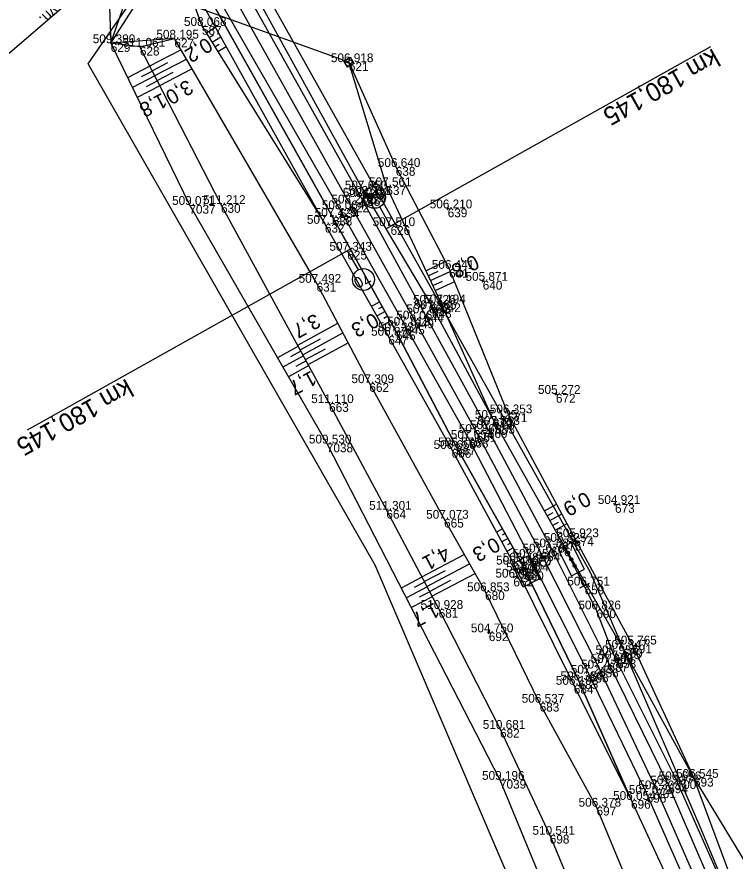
# Model space of a CAD drawing. Extents: x -1234191 to 23050, y -1290331 to -741191.
# Drawn here: x -865261.3 to -865163.3, y -1106049.8 to -1105934.7 of the extents above; entities that cross this region are included whole.
import ezdxf

# ---------------------------------------------------------------- set-up
doc = ezdxf.new("R2010")
doc.units = 0
for name, color, linetype in [('Vrstva 1', 7, 'Continuous'), ('Vrstva 25', 7, 'Continuous'), ('Vrstva 36', 7, 'Continuous'), ('Vrstva 4', 7, 'Continuous'), ('Vrstva 48', 7, 'Continuous'), ('Vrstva 49', 7, 'Continuous'), ('Vrstva 5', 7, 'Continuous'), ('Vrstva 51', 7, 'Continuous'), ('Vrstva 53', 7, 'Continuous'), ('Vrstva 55', 7, 'Continuous'), ('Vrstva 60', 7, 'Continuous'), ('Vrstva 61', 7, 'Continuous'), ('Vrstva 7', 7, 'Continuous')]:
    doc.layers.add(name, color=color, linetype=linetype)

msp = doc.modelspace()

# ---------------------------------------------------------------- linework, layer by layer
at = {"layer": 'Vrstva 1'}
msp.add_lwpolyline([(-865311.67, -1105789.32), (-865293.8, -1105821.19), (-865269.3, -1105864.9), (-865244.89, -1105908.45), (-865242.92, -1105911.97), (-865241.31, -1105914.84), (-865239.97, -1105917.2), (-865237.77, -1105921.12), (-865236.43, -1105923.5), (-865235.71, -1105924.79), (-865215.93, -1105960.12), (-865207.08, -1105975.94), (-865198.56, -1105991.42), (-865189.87, -1106007.72), (-865181.88, -1106023.53), (-865174.08, -1106040), (-865166.92, -1106056.41)], dxfattribs=at)
at = {"layer": 'Vrstva 25'}
msp.add_line((-865216, -1105940.86), (-865305.81, -1105908.49), dxfattribs=at)
at = {"layer": 'Vrstva 36'}
for p, q in [((-865216.62, -1105940.77), (-865215.42, -1105941.11)), ((-865216.28, -1105940.45), (-865215.54, -1105940.66)), ((-865216.35, -1105941.26), (-865215.91, -1105941.39))]:
    msp.add_line(p, q, dxfattribs=at)
msp.add_lwpolyline([(-865215.81, -1105940.18), (-865215.32, -1105941.05), (-865216.19, -1105941.54), (-865216.68, -1105940.67), (-865215.81, -1105940.18)], dxfattribs=at)
at = {"layer": 'Vrstva 4'}
for points in [[(-865236.51, -1105919.7), (-865214.37, -1105959.25), (-865205.71, -1105975.1), (-865197.04, -1105990.91), (-865188.45, -1106007.02), (-865180.58, -1106022.78), (-865172.44, -1106039.34), (-865165.47, -1106055.61), (-865156.6, -1106078.95), (-865148.77, -1106102.82), (-865142.37, -1106126.99), (-865137.15, -1106151.58), (-865133.37, -1106176.49), (-865130.91, -1106201.27), (-865129.85, -1106218.85), (-865129.68, -1106236.02), (-865129.85, -1106253.8), (-865130.86, -1106271.38), (-865132.17, -1106288.96), (-865133.64, -1106306.37), (-865136.71, -1106335.02), (-865140.22, -1106364.77), (-865141.26, -1106380.09)], [(-865164.28, -1106054.67), (-865171.3, -1106038.77), (-865179.91, -1106021.58), (-865182.25, -1106015.47), (-865186.96, -1106006.27), (-865196.36, -1105989.49), (-865204.8, -1105973.8), (-865214.1, -1105958.2), (-865230.93, -1105927.64), (-865233.02, -1105923.82), (-865233.43, -1105924.05), (-865235.15, -1105921.01), (-865234.74, -1105920.78), (-865236.51, -1105919.7)], [(-865168.18, -1106056.94), (-865175.38, -1106040.63), (-865183.27, -1106024.24), (-865191.23, -1106008.42), (-865199.64, -1105992.22), (-865208.33, -1105976.78), (-865217.24, -1105960.91), (-865239.73, -1105921.76), (-865239.36, -1105923.22), (-865237.67, -1105926.18), (-865238.09, -1105926.42), (-865236.15, -1105929.98), (-865218.21, -1105961.95), (-865209.58, -1105977.54), (-865201.36, -1105993.24), (-865192.55, -1106008.96), (-865184.68, -1106025.13), (-865177.51, -1106041.45), (-865169.99, -1106057.67)]]:
    msp.add_lwpolyline(points, dxfattribs=at)
at = {"layer": 'Vrstva 48'}
for p, q in [((-865235.44, -1105936.86), (-865234.19, -1105936.08)), ((-865235.05, -1105937.5), (-865234.44, -1105937.12)), ((-865234.65, -1105938.14), (-865233.46, -1105937.4)), ((-865234.26, -1105938.77), (-865233.68, -1105938.41)), ((-865243.16, -1105941.35), (-865238.91, -1105939.16)), ((-865233.86, -1105939.41), (-865232.73, -1105938.71)), ((-865242.47, -1105942.68), (-865238.16, -1105940.46)), ((-865243.13, -1105941.4), (-865246.19, -1105942.98)), ((-865242.82, -1105942.02), (-865240.68, -1105940.91)), ((-865241.79, -1105944.02), (-865237.4, -1105941.75)), ((-865242.45, -1105942.74), (-865245.53, -1105944.33)), ((-865242.79, -1105942.07), (-865244.32, -1105942.86)), ((-865242.13, -1105943.35), (-865239.96, -1105942.23)), ((-865241.76, -1105944.07), (-865244.87, -1105945.68)), ((-865242.1, -1105943.4), (-865243.65, -1105944.2)), ((-865205.5, -1105969.29), (-865202.85, -1105968.05)), ((-865205.18, -1105969.97), (-865203.84, -1105969.34)), ((-865204.86, -1105970.65), (-865202.19, -1105969.4)), ((-865204.54, -1105971.33), (-865203.22, -1105970.71)), ((-865204.22, -1105972.01), (-865201.62, -1105970.79)), ((-865211.79, -1105973.54), (-865212.89, -1105974.15)), ((-865211.07, -1105974.86), (-865212.15, -1105975.46)), ((-865211.43, -1105974.2), (-865211.97, -1105974.5)), ((-865222.98, -1105979.44), (-865217.5, -1105976.45)), ((-865210.34, -1105976.17), (-865211.41, -1105976.76)), ((-865210.7, -1105975.51), (-865211.24, -1105975.81)), ((-865222.63, -1105980.09), (-865219.89, -1105978.6)), ((-865222.27, -1105980.75), (-865216.8, -1105977.78)), ((-865222.89, -1105979.6), (-865225.74, -1105981.15)), ((-865221.91, -1105981.41), (-865219.18, -1105979.93)), ((-865221.55, -1105982.07), (-865216.1, -1105979.11)), ((-865222.18, -1105980.92), (-865224.99, -1105982.45)), ((-865222.54, -1105980.26), (-865223.95, -1105981.03)), ((-865221.82, -1105981.58), (-865223.22, -1105982.34)), ((-865221.46, -1105982.24), (-865224.24, -1105983.75)), ((-865189.32, -1106002.05), (-865187.67, -1106001.13)), ((-865188.95, -1106002.71), (-865188.14, -1106002.25)), ((-865188.59, -1106003.36), (-865186.96, -1106002.45)), ((-865188.22, -1106004.02), (-865187.41, -1106003.57)), ((-865187.85, -1106004.67), (-865186.25, -1106003.78)), ((-865195.06, -1106004.49), (-865195.86, -1106004.94)), ((-865194.69, -1106005.14), (-865195.09, -1106005.37)), ((-865194.32, -1106005.79), (-865195.14, -1106006.26)), ((-865193.59, -1106007.1), (-865194.43, -1106007.57)), ((-865193.96, -1106006.45), (-865194.37, -1106006.68)), ((-865206.06, -1106011.02), (-865200.27, -1106007.97)), ((-865205.36, -1106012.35), (-865199.53, -1106009.28)), ((-865205.71, -1106011.69), (-865202.81, -1106010.16)), ((-865204.67, -1106013.68), (-865198.79, -1106010.58)), ((-865206.03, -1106011.08), (-865208.85, -1106012.57)), ((-865205.68, -1106011.75), (-865207.09, -1106012.49)), ((-865205.02, -1106013.02), (-865202.09, -1106011.47)), ((-865205.33, -1106012.41), (-865208.16, -1106013.9)), ((-865204.98, -1106013.07), (-865206.4, -1106013.82)), ((-865204.64, -1106013.74), (-865207.47, -1106015.23))]:
    msp.add_line(p, q, dxfattribs=at)
at = {"layer": 'Vrstva 49'}
for p, q in [((-865239.79, -1105937.65), (-865248.48, -1105938.27)), ((-865244.5, -1105938.75), (-865248.48, -1105938.27)), ((-865244.5, -1105938.75), (-865239.79, -1105937.65)), ((-865202.76, -1105960.73), (-865202.27, -1105960.86)), ((-865202.45, -1105960.55), (-865202.58, -1105961.04)), ((-865197.98, -1105970.6), (-865197.5, -1105970.74)), ((-865197.67, -1105970.43), (-865197.8, -1105970.91)), ((-865188, -1105986.02), (-865187.52, -1105986.16)), ((-865187.69, -1105985.85), (-865187.83, -1105986.33)), ((-865179.94, -1106001.03), (-865179.46, -1106001.17)), ((-865179.62, -1106000.86), (-865179.77, -1106001.34)), ((-865197.15, -1106018.52), (-865196.67, -1106018.68)), ((-865196.83, -1106018.36), (-865196.99, -1106018.84))]:
    msp.add_line(p, q, dxfattribs=at)
for points in [[(-865239.87, -1105923.51), (-865244.4, -1105924.73), (-865248.77, -1105929.71), (-865248.48, -1105938.27)], [(-865248.48, -1105938.27), (-865245.36, -1105929.31), (-865242.58, -1105925.9), (-865239.87, -1105923.51)], [(-865248.48, -1105938.27), (-865244.7, -1105932.37), (-865240.18, -1105924.98)], [(-865177.51, -1106041.45), (-865185.32, -1106025.75), (-865193.46, -1106009.36), (-865201.99, -1105993.6), (-865210.62, -1105978.16), (-865219.27, -1105962.9), (-865235.91, -1105933), (-865239.58, -1105926.15)], [(-865239.58, -1105926.15), (-865236.03, -1105935.92), (-865219.27, -1105962.9)], [(-865177.51, -1106041.45), (-865184.68, -1106025.13), (-865192.55, -1106008.96), (-865201.36, -1105993.24), (-865209.58, -1105977.54), (-865218.21, -1105961.95), (-865236.15, -1105929.98), (-865238.09, -1105926.42)], [(-865248.48, -1105938.27), (-865237.75, -1105960.32), (-865219, -1105992.85), (-865195.39, -1106038.71), (-865183.02, -1106068.8), (-865169.19, -1106106.68), (-865159.48, -1106146.73), (-865152.52, -1106195.61), (-865150.4, -1106228.21), (-865150, -1106273.86), (-865151.77, -1106298.15), (-865154.53, -1106323.47), (-865155.1, -1106347.33), (-865155.48, -1106356.04)], [(-865145.94, -1106363.57), (-865142.64, -1106334.62), (-865139.29, -1106305.46), (-865137.62, -1106288.58), (-865139.33, -1106271.91), (-865139.98, -1106253.67), (-865139.71, -1106236.34), (-865140.16, -1106218.63), (-865140.5, -1106202.16), (-865143.15, -1106177.89), (-865147.63, -1106152.54), (-865151.89, -1106128.68), (-865158.01, -1106106.65), (-865166.09, -1106083.22), (-865174.81, -1106060.27), (-865182.22, -1106042.37), (-865189.98, -1106028.2), (-865197.42, -1106013), (-865203.01, -1106003.11), (-865213.2, -1105984.62), (-865220.4, -1105970.94), (-865239.79, -1105937.65)], [(-865155.48, -1106356.04), (-865151.68, -1106354.48), (-865149.3, -1106324.02), (-865147.43, -1106302.26), (-865147.23, -1106283.88), (-865146.7, -1106266.35), (-865146.43, -1106254.76), (-865146.52, -1106236.51), (-865147.19, -1106221.06), (-865147.91, -1106203.33), (-865150.13, -1106177.77), (-865154.11, -1106153.82), (-865158.52, -1106132.86), (-865164.63, -1106109.25), (-865174.13, -1106081.15), (-865182.3, -1106061.24), (-865188.6, -1106046.2), (-865195.38, -1106031.76), (-865203.75, -1106015.41), (-865210.88, -1106001.89), (-865218.69, -1105987.34), (-865233.44, -1105960.2), (-865244.5, -1105938.75)], [(-865127.37, -1106218.56), (-865127, -1106201.04), (-865129.61, -1106175.31), (-865133.23, -1106150.78), (-865138.55, -1106126.31), (-865140.86, -1106117.48), (-865147.92, -1106094.71), (-865153.79, -1106077.74), (-865163.01, -1106054.44), (-865168.93, -1106038.44), (-865178.61, -1106020.85), (-865186.96, -1106006.27), (-865196.36, -1105989.49), (-865203.41, -1105973.74), (-865210.89, -1105957.77), (-865216, -1105940.86)], [(-865216, -1105940.86), (-865209.6, -1105955.15), (-865202.33, -1105969.04), (-865194.33, -1105988.74), (-865185.26, -1106005.63), (-865177.36, -1106020.26), (-865168.93, -1106038.44), (-865158.94, -1106054.9), (-865150.77, -1106078.05), (-865143.25, -1106101.54), (-865134.36, -1106126.45), (-865131.26, -1106149.56), (-865127.17, -1106172.7), (-865123.9, -1106198.3), (-865127.37, -1106218.56)]]:
    msp.add_lwpolyline(points, dxfattribs=at)
at = {"layer": 'Vrstva 5'}
for p, q in [((-865166.69, -1105938.77), (-865210.31, -1105963.21)), ((-865210.31, -1105963.21), (-865211.77, -1105960.59)), ((-865210.96, -1105963.58), (-865209.65, -1105962.84)), ((-865259.83, -1105991.01), (-865216.21, -1105966.57)), ((-865215.56, -1105966.2), (-865216.86, -1105966.93)), ((-865216.21, -1105966.57), (-865214.74, -1105969.18))]:
    msp.add_line(p, q, dxfattribs=at)
for centre in [(-865212.51, -1105959.28), (-865214.01, -1105970.49)]:
    msp.add_circle(centre, 1.5, dxfattribs=at)
at = {"layer": 'Vrstva 53'}
for points in [[(-865227.66, -1105917.88), (-865232.36, -1105922.35), (-865183.09, -1106010.41), (-865167.99, -1106045.38), (-865144.78, -1106101.17), (-865131.99, -1106166.39), (-865125.85, -1106219.01), (-865125.39, -1106238.65), (-865125.96, -1106278.9), (-865132.87, -1106334.65), (-865136.85, -1106381.38), (-865151.63, -1106445.1), (-865163.44, -1106490.83), (-865178.82, -1106535.04), (-865200.93, -1106584.09), (-865238.82, -1106657.44), (-865256.95, -1106698.52)], [(-865292.28, -1106759.44), (-865281, -1106690.92), (-865292.09, -1106688.29), (-865256.12, -1106617.24), (-865192.39, -1106497.22), (-865182.07, -1106466.18), (-865172.59, -1106441.08), (-865160.97, -1106443.62), (-865159.33, -1106435.02), (-865146.44, -1106359.55), (-865157.51, -1106356.95), (-865157, -1106331.91), (-865151.9, -1106265.92), (-865152.14, -1106213.17), (-865160.59, -1106155.82), (-865173.12, -1106100.65), (-865192.84, -1106055.27), (-865212.4, -1106009.43), (-865251.57, -1105941.08), (-865241.97, -1105927.13)]]:
    msp.add_lwpolyline(points, dxfattribs=at)
at = {"layer": 'Vrstva 55'}
msp.add_lwpolyline([(-865243.93, -1105923.83), (-865276.72, -1105952), (-865303.41, -1105968.16)], dxfattribs=at)
at = {"layer": 'Vrstva 60'}
for p, q in [((-865236.03, -1105935.92), (-865236.03, -1105935.92)), ((-865248.48, -1105938.27), (-865248.48, -1105938.27)), ((-865239.79, -1105937.65), (-865239.79, -1105937.65)), ((-865244.5, -1105938.75), (-865244.5, -1105938.75)), ((-865216, -1105940.86), (-865216, -1105940.86)), ((-865209.6, -1105955.15), (-865209.6, -1105955.15)), ((-865210.89, -1105957.77), (-865210.89, -1105957.77)), ((-865214.1, -1105958.2), (-865214.1, -1105958.2)), ((-865213.6, -1105958.96), (-865213.6, -1105958.96)), ((-865237.75, -1105960.32), (-865237.75, -1105960.32)), ((-865233.44, -1105960.2), (-865233.44, -1105960.2)), ((-865215.93, -1105960.12), (-865215.93, -1105960.12)), ((-865214.37, -1105959.25), (-865214.37, -1105959.25)), ((-865217.24, -1105960.91), (-865217.24, -1105960.91)), ((-865202.52, -1105960.79), (-865202.52, -1105960.79)), ((-865218.21, -1105961.95), (-865218.21, -1105961.95)), ((-865219.27, -1105962.9), (-865219.27, -1105962.9)), ((-865210.31, -1105963.21), (-865210.31, -1105963.21)), ((-865216.21, -1105966.57), (-865216.21, -1105966.57)), ((-865202.33, -1105969.04), (-865202.33, -1105969.04)), ((-865197.74, -1105970.67), (-865197.74, -1105970.67)), ((-865220.4, -1105970.94), (-865220.4, -1105970.94)), ((-865204.8, -1105973.8), (-865204.8, -1105973.8)), ((-865203.41, -1105973.74), (-865203.41, -1105973.74)), ((-865205.71, -1105975.1), (-865205.71, -1105975.1)), ((-865204.67, -1105974.52), (-865204.67, -1105974.52)), ((-865207.08, -1105975.94), (-865207.08, -1105975.94)), ((-865209.58, -1105977.54), (-865209.58, -1105977.54)), ((-865208.33, -1105976.78), (-865208.33, -1105976.78)), ((-865210.62, -1105978.16), (-865210.62, -1105978.16)), ((-865213.2, -1105984.62), (-865213.2, -1105984.62)), ((-865187.76, -1105986.09), (-865187.76, -1105986.09)), ((-865218.69, -1105987.34), (-865218.69, -1105987.34)), ((-865194.33, -1105988.74), (-865194.33, -1105988.74)), ((-865196.36, -1105989.49), (-865196.36, -1105989.49)), ((-865198.56, -1105991.42), (-865198.56, -1105991.42)), ((-865197.04, -1105990.91), (-865197.04, -1105990.91)), ((-865196.03, -1105990.31), (-865196.03, -1105990.31)), ((-865199.64, -1105992.22), (-865199.64, -1105992.22)), ((-865219, -1105992.85), (-865219, -1105992.85)), ((-865201.99, -1105993.6), (-865201.99, -1105993.6)), ((-865201.36, -1105993.24), (-865201.36, -1105993.24)), ((-865179.7, -1106001.1), (-865179.7, -1106001.1)), ((-865210.88, -1106001.89), (-865210.88, -1106001.89)), ((-865203.01, -1106003.11), (-865203.01, -1106003.11)), ((-865186.96, -1106006.27), (-865186.96, -1106006.27)), ((-865185.26, -1106005.63), (-865185.26, -1106005.63)), ((-865188.45, -1106007.02), (-865188.45, -1106007.02)), ((-865191.23, -1106008.42), (-865191.23, -1106008.42)), ((-865189.87, -1106007.72), (-865189.87, -1106007.72)), ((-865193.46, -1106009.36), (-865193.46, -1106009.36)), ((-865192.55, -1106008.96), (-865192.55, -1106008.96)), ((-865192.1, -1106010.3), (-865192.1, -1106010.3)), ((-865193.56, -1106011.14), (-865193.56, -1106011.14)), ((-865197.42, -1106013), (-865197.42, -1106013)), ((-865183.85, -1106012.22), (-865183.85, -1106012.22)), ((-865203.75, -1106015.41), (-865203.75, -1106015.41)), ((-865182.25, -1106015.47), (-865182.25, -1106015.47)), ((-865196.91, -1106018.6), (-865196.91, -1106018.6)), ((-865178.61, -1106020.85), (-865178.61, -1106020.85)), ((-865177.36, -1106020.26), (-865177.36, -1106020.26)), ((-865179.91, -1106021.58), (-865179.91, -1106021.58)), ((-865179.5, -1106022.28), (-865179.5, -1106022.28)), ((-865181.88, -1106023.53), (-865181.88, -1106023.53)), ((-865180.58, -1106022.78), (-865180.58, -1106022.78)), ((-865183.27, -1106024.24), (-865183.27, -1106024.24)), ((-865185.32, -1106025.75), (-865185.32, -1106025.75)), ((-865184.68, -1106025.13), (-865184.68, -1106025.13)), ((-865189.98, -1106028.2), (-865189.98, -1106028.2)), ((-865195.38, -1106031.76), (-865195.38, -1106031.76)), ((-865168.93, -1106038.44), (-865168.93, -1106038.44)), ((-865195.39, -1106038.71), (-865195.39, -1106038.71)), ((-865172.44, -1106039.34), (-865172.44, -1106039.34)), ((-865171.3, -1106038.77), (-865171.3, -1106038.77)), ((-865175.38, -1106040.63), (-865175.38, -1106040.63)), ((-865174.08, -1106040), (-865174.08, -1106040)), ((-865177.51, -1106041.45), (-865177.51, -1106041.45)), ((-865182.22, -1106042.37), (-865182.22, -1106042.37)), ((-865188.6, -1106046.2), (-865188.6, -1106046.2))]:
    msp.add_line(p, q, dxfattribs=at)
at = {"layer": 'Vrstva 7'}
for p, q in [((-865213.16, -1105958.72), (-865214.03, -1105959.21)), ((-865213.84, -1105958.53), (-865213.35, -1105959.4)), ((-865204.91, -1105974.08), (-865204.42, -1105974.96)), ((-865204.23, -1105974.27), (-865205.1, -1105974.76)), ((-865195.59, -1105990.07), (-865196.47, -1105990.55)), ((-865196.26, -1105989.87), (-865195.79, -1105990.75)), ((-865186.06, -1106007.56), (-865186.18, -1106007.94)), ((-865185.6, -1106008.46), (-865185.72, -1106008.83)), ((-865185.15, -1106009.35), (-865185.27, -1106009.73)), ((-865193.56, -1106011.14), (-865193, -1106010.86)), ((-865192.12, -1106010.25), (-865192.08, -1106010.34)), ((-865184.52, -1106012.55), (-865183.19, -1106011.88)), ((-865179.05, -1106022.06), (-865179.95, -1106022.51)), ((-865179.73, -1106021.84), (-865179.28, -1106022.73))]:
    msp.add_line(p, q, dxfattribs=at)
msp.add_lwpolyline([(-865183.85, -1106012.22), (-865184.76, -1106010.43), (-865183.86, -1106009.98), (-865185.67, -1106006.41), (-865187.45, -1106007.31), (-865185.65, -1106010.88), (-865184.76, -1106010.43)], dxfattribs=at)
msp.add_lwpolyline([(-865193.79, -1106009.31), (-865191.57, -1106008.19), (-865190, -1106011.3), (-865192.21, -1106012.42)], close=True, dxfattribs=at)
for centre, radius in [((-865186.11, -1106007.75), 0.2), ((-865189.28, -1106008.88), 0.75), ((-865185.66, -1106008.65), 0.2), ((-865192.1, -1106010.3), 0.5), ((-865185.21, -1106009.54), 0.2)]:
    msp.add_circle(centre, radius, dxfattribs=at)

# ---------------------------------------------------------------- texts
at = {"layer": 'Vrstva 48'}
for s, rotation, p in [('0,2', 211.852, (-865235.42, -1105937.4)), ('3,0', 210.2274, (-865238, -1105943.16)), ('1,8', 207.2794, (-865241.48, -1105944.99)), ('0,8', 205.0828, (-865198.86, -1105967.05)), ('3,7', 208.5277, (-865220.59, -1105975.06)), ('0,3', 208.9637, (-865212.63, -1105974.95)), ('1,7', 208.5277, (-865221.11, -1105982.85)), ('0,9', 209.2429, (-865183.74, -1105999.33)), ('0,3', 209.271, (-865196.1, -1106005.54)), ('4,1', 207.7908, (-865202.89, -1106006.76)), ('1,7', 207.7908, (-865204.32, -1106014.47))]:
    msp.add_text(s, height=2, rotation=rotation, dxfattribs=at).set_placement(p)
at = {"layer": 'Vrstva 5'}
for s, height, rotation, p in [('km 180,145', 2.5, 209.2657, (-865166.34, -1105938.92)), ('80', 1.5, 29.2657, (-865212.94, -1105960.38)), ('70', 1.5, 209.2657, (-865213.58, -1105969.39)), ('km 180,145', 2.5, 209.2657, (-865246.35, -1105983.95))]:
    msp.add_text(s, height=height, rotation=rotation, dxfattribs=at).set_placement(p)
at = {"layer": 'Vrstva 51'}
msp.add_text('nezpevn.', height=1.5, rotation=223.4189, dxfattribs=at).set_placement((-865252.47, -1105929.25))
at = {"layer": 'Vrstva 60'}
for s, p in [('587', (-865236.03, -1105937.12)), ('629', (-865248.48, -1105939.47)), ('627', (-865239.79, -1105938.85)), ('628', (-865244.5, -1105939.95)), ('621', (-865216, -1105942.06)), ('638', (-865209.6, -1105956.35)), ('637', (-865210.89, -1105958.97)), ('636', (-865214.1, -1105959.4)), ('624', (-865213.6, -1105960.16)), ('7037', (-865237.75, -1105961.52)), ('630', (-865233.44, -1105961.4)), ('622', (-865215.93, -1105961.32)), ('635', (-865214.37, -1105960.45)), ('634', (-865217.24, -1105962.11)), ('639', (-865202.52, -1105962)), ('633', (-865218.21, -1105963.15)), ('632', (-865219.27, -1105964.1)), ('626', (-865210.31, -1105964.41)), ('625', (-865216.21, -1105967.77)), ('641', (-865202.33, -1105970.24)), ('640', (-865197.74, -1105971.87)), ('631', (-865220.4, -1105972.14)), ('643', (-865204.8, -1105975)), ('642', (-865203.41, -1105974.94)), ('644', (-865205.71, -1105976.3)), ('648', (-865204.67, -1105975.72)), ('649', (-865207.08, -1105977.14)), ('646', (-865209.58, -1105978.74)), ('645', (-865208.33, -1105977.98)), ('647', (-865210.62, -1105979.36)), ('662', (-865213.2, -1105985.82)), ('672', (-865187.76, -1105987.29)), ('663', (-865218.69, -1105988.54)), ('671', (-865194.33, -1105989.94)), ('670', (-865196.36, -1105990.69)), ('653', (-865196.03, -1105991.51)), ('651', (-865198.56, -1105992.62)), ('669', (-865197.04, -1105992.11)), ('668', (-865199.64, -1105993.42)), ('7038', (-865219, -1105994.05)), ('666', (-865201.99, -1105994.8)), ('667', (-865201.36, -1105994.44)), ('673', (-865179.7, -1106002.3)), ('664', (-865210.88, -1106003.09)), ('665', (-865203.01, -1106004.31)), ('675', (-865186.96, -1106007.47)), ('674', (-865185.26, -1106006.83)), ('676', (-865188.45, -1106008.22)), ('677', (-865191.23, -1106009.62)), ('654', (-865189.87, -1106008.92)), ('679', (-865193.46, -1106010.56)), ('678', (-865192.55, -1106010.16)), ('660', (-865192.1, -1106011.5)), ('661', (-865193.56, -1106012.34)), ('680', (-865197.42, -1106014.2)), ('659', (-865183.85, -1106013.42)), ('681', (-865203.75, -1106016.61)), ('690', (-865182.25, -1106016.67)), ('692', (-865196.91, -1106019.8)), ('689', (-865178.61, -1106022.05)), ('691', (-865177.36, -1106021.46)), ('688', (-865179.91, -1106022.78)), ('658', (-865179.5, -1106023.48)), ('656', (-865181.88, -1106024.74)), ('687', (-865180.58, -1106023.98)), ('686', (-865183.27, -1106025.44)), ('684', (-865185.32, -1106026.95)), ('685', (-865184.68, -1106026.33)), ('683', (-865189.98, -1106029.4)), ('682', (-865195.38, -1106032.96)), ('693', (-865168.93, -1106039.64)), ('7039', (-865195.39, -1106039.91)), ('694', (-865172.44, -1106040.54)), ('700', (-865171.3, -1106039.97)), ('695', (-865175.38, -1106041.83)), ('701', (-865174.08, -1106041.2)), ('696', (-865177.51, -1106042.65)), ('697', (-865182.22, -1106043.57)), ('698', (-865188.6, -1106047.4))]:
    msp.add_text(s, height=1.2, dxfattribs=at).set_placement(p)
at = {"layer": 'Vrstva 61'}
for s, p in [('508.068', (-865238.49, -1105935.92)), ('509.390', (-865250.93, -1105938.27)), ('508.195', (-865242.25, -1105937.65)), ('511.061', (-865246.86, -1105938.75)), ('506.918', (-865218.45, -1105940.86)), ('506.640', (-865212.05, -1105955.15)), ('507.561', (-865213.25, -1105957.77)), ('508.043', (-865216.82, -1105959.25)), ('507.650', (-865216.55, -1105958.2)), ('508.218', (-865216.05, -1105958.96)), ('509.071', (-865240.11, -1105960.32)), ('511.212', (-865235.89, -1105960.2)), ('508.272', (-865218.38, -1105960.12)), ('508.064', (-865219.69, -1105960.91)), ('506.210', (-865204.97, -1105960.79)), ('507.429', (-865220.66, -1105961.95)), ('507.143', (-865221.72, -1105962.9)), ('507.510', (-865212.76, -1105963.21)), ('507.343', (-865218.66, -1105966.57)), ('506.441', (-865204.69, -1105969.04)), ('505.871', (-865200.09, -1105970.67)), ('507.492', (-865222.85, -1105970.94)), ('507.326', (-865207.25, -1105973.8)), ('507.194', (-865205.86, -1105973.74)), ('507.892', (-865208.16, -1105975.1)), ('507.965', (-865207.12, -1105974.52)), ('508.067', (-865209.53, -1105975.94)), ('507.237', (-865212.03, -1105977.54)), ('507.812', (-865210.78, -1105976.78)), ('506.871', (-865212.97, -1105978.16)), ('507.309', (-865215.65, -1105984.62)), ('505.272', (-865190.21, -1105986.09)), ('511.110', (-865221.14, -1105987.34)), ('506.353', (-865196.78, -1105988.74)), ('507.125', (-865198.81, -1105989.49)), ('507.818', (-865198.48, -1105990.31)), ('507.869', (-865201.01, -1105991.42)), ('507.743', (-865199.49, -1105990.91)), ('507.654', (-865202.09, -1105992.22)), ('509.530', (-865221.45, -1105992.85)), ('506.658', (-865204.44, -1105993.6)), ('506.875', (-865203.82, -1105993.24)), ('504.921', (-865182.05, -1106001.1)), ('511.301', (-865213.23, -1106001.89)), ('507.073', (-865205.46, -1106003.11)), ('506.825', (-865189.41, -1106006.27)), ('505.923', (-865187.71, -1106005.63)), ('507.587', (-865190.9, -1106007.02)), ('507.450', (-865193.68, -1106008.42)), ('507.670', (-865192.32, -1106007.72)), ('506.486', (-865195.92, -1106009.36)), ('506.785', (-865195, -1106008.96)), ('507.304', (-865194.55, -1106010.3)), ('506.589', (-865196.01, -1106011.14)), ('506.751', (-865186.21, -1106012.22)), ('506.853', (-865199.88, -1106013)), ('510.928', (-865206.21, -1106015.41)), ('506.826', (-865184.7, -1106015.47)), ('504.750', (-865199.36, -1106018.6)), ('505.765', (-865179.81, -1106020.26)), ('507.347', (-865181.06, -1106020.85)), ('506.957', (-865182.36, -1106021.58)), ('507.475', (-865181.96, -1106022.28)), ('507.475', (-865184.33, -1106023.53)), ('507.409', (-865183.03, -1106022.78)), ('507.245', (-865185.73, -1106024.24)), ('506.193', (-865187.78, -1106025.75)), ('506.386', (-865187.14, -1106025.13)), ('506.537', (-865192.43, -1106028.2)), ('510.681', (-865197.74, -1106031.76)), ('506.545', (-865171.38, -1106038.44)), ('509.196', (-865197.84, -1106038.71)), ('507.237', (-865174.89, -1106039.34)), ('506.656', (-865173.75, -1106038.77)), ('507.072', (-865177.82, -1106040.63)), ('507.303', (-865176.53, -1106040)), ('506.054', (-865179.96, -1106041.45)), ('506.378', (-865184.67, -1106042.37)), ('510.541', (-865190.96, -1106046.2))]:
    msp.add_text(s, height=1.2, dxfattribs=at).set_placement(p)
at = {"layer": 'Vrstva 7'}
msp.add_text('KM', height=1.247, rotation=296.8022, dxfattribs=at).set_placement((-865192.91, -1106009.68))

doc.saveas('drawing.dxf')
